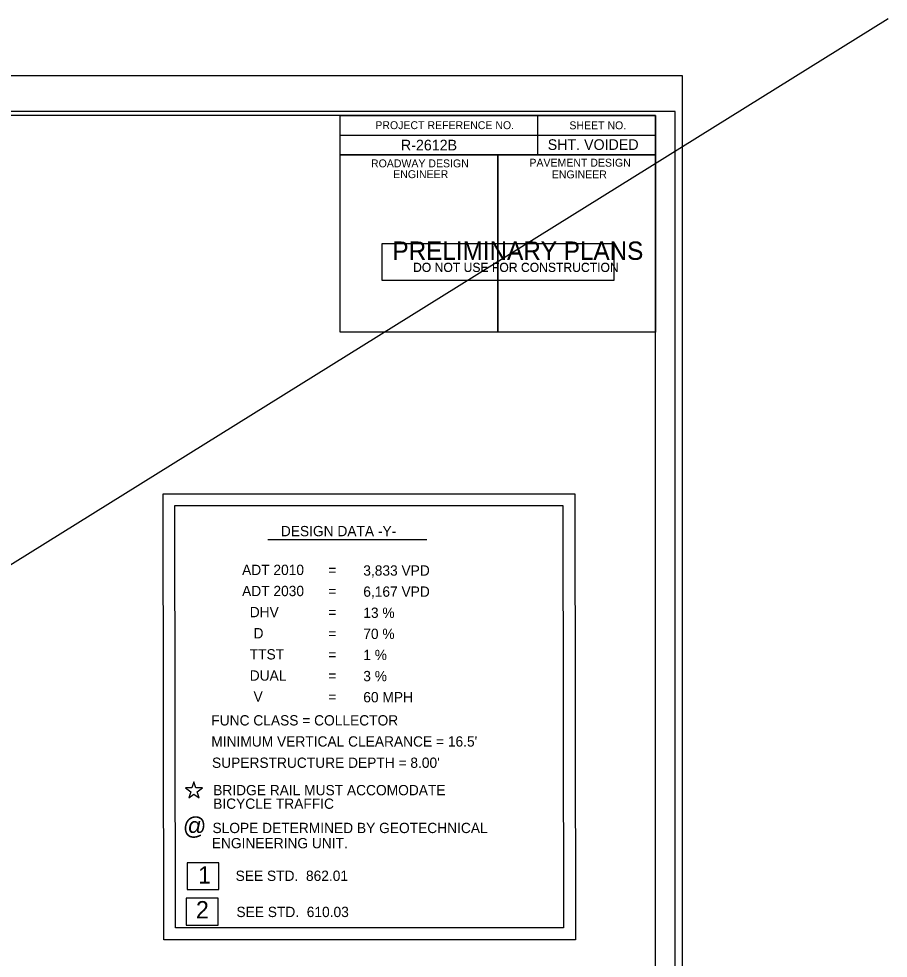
# Model space of a CAD drawing. Extents: x 573813 to 575363, y -54752 to -53123.
# Drawn here: x 574087.2 to 574197.6, y -54636.2 to -54516.9 of the extents above; entities that cross this region are included whole.
import ezdxf

# ---------------------------------------------------------------- set-up
doc = ezdxf.new("R2010")
doc.units = 0
for name, color, linetype in [('Old_Level_11', 7, 'Continuous'), ('Prop RDY Traffic Signal CELL', 7, 'Continuous'), ('Sheet Data Field CELL', 7, 'Continuous'), ('Sheet Plot Border Inside CELL', 7, 'Continuous'), ('Sheet Plot Border Outside CELL', 7, 'Continuous'), ('Sheet Sticker Preliminary CELL', 7, 'Continuous'), ('Sheet Typical CELL', 7, 'Continuous')]:
    doc.layers.add(name, color=color, linetype=linetype)

msp = doc.modelspace()

# ---------------------------------------------------------------- linework, layer by layer
at = {"layer": 'Old_Level_11'}
for p, q in [((574197.59, -54516.9), (573819.63, -54751.97)), ((574118.8, -54583.01), (574138.99, -54583.01))]:
    msp.add_line(p, q, dxfattribs=at)
for points in [[(574105.51, -54577.2), (574157.78, -54577.2), (574157.88, -54633.8), (574105.61, -54633.8)], [(574107.01, -54578.7), (574156.28, -54578.7), (574156.37, -54632.3), (574107.1, -54632.3)], [(574108.55, -54627.44), (574112.59, -54627.44), (574112.59, -54624.04), (574108.55, -54624.04)], [(574108.45, -54631.95), (574112.5, -54631.95), (574112.5, -54628.55), (574108.45, -54628.55)]]:
    msp.add_lwpolyline(points, close=True, dxfattribs=at)
at = {"layer": 'Prop RDY Traffic Signal CELL'}
msp.add_lwpolyline([(574109.17, -54614.54), (574108.36, -54614.54), (574109.02, -54615.02), (574108.76, -54615.8), (574109.43, -54615.32), (574110.09, -54615.8), (574109.83, -54615.02), (574110.5, -54614.54), (574109.68, -54614.54), (574109.42, -54613.77), (574109.17, -54614.54)], dxfattribs=at)
at = {"layer": 'Sheet Plot Border Inside CELL'}
msp.add_lwpolyline([(574170.55, -54528.66), (573837.07, -54528.66), (573837.07, -54739.79), (574170.55, -54739.79)], close=True, dxfattribs=at)
at = {"layer": 'Sheet Plot Border Outside CELL'}
for p, q in [((574171.45, -54524.16), (573834.47, -54524.16)), ((574171.45, -54744.28), (574171.45, -54524.16))]:
    msp.add_line(p, q, dxfattribs=at)
msp.add_lwpolyline([(574171.45, -54524.16), (573834.47, -54524.16), (573834.47, -54744.28), (574171.45, -54744.28)], close=True, dxfattribs=at)
at = {"layer": 'Sheet Sticker Preliminary CELL'}
for points in [[(574133.33, -54550.11), (574133.33, -54545.41), (574162.74, -54545.41), (574162.74, -54550.11)], [(574133.33, -54550.14), (574133.33, -54545.44), (574162.74, -54545.44), (574162.74, -54550.14)]]:
    msp.add_lwpolyline(points, close=True, dxfattribs=at)
at = {"layer": 'Sheet Typical CELL'}
for p, q in [((574153.04, -54529.18), (574153.04, -54534.18)), ((574128.01, -54531.68), (574168.04, -54531.68)), ((574148.03, -54534.18), (574148.03, -54556.68))]:
    msp.add_line(p, q, dxfattribs=at)
for points in [[(574168.04, -54529.17), (573867.88, -54529.17), (573867.88, -54739.28), (574168.04, -54739.28)], [(574128.01, -54529.17), (574168.04, -54529.17), (574168.04, -54534.18), (574128.01, -54534.18)], [(574128.01, -54534.18), (574148.03, -54534.18), (574148.03, -54556.69), (574128.01, -54556.69)], [(574148.03, -54534.18), (574168.04, -54534.18), (574168.04, -54556.69), (574148.03, -54556.69)]]:
    msp.add_lwpolyline(points, close=True, dxfattribs=at)

# ---------------------------------------------------------------- texts
at = {"layer": 'Old_Level_11'}
for s, height, p in [('DESIGN DATA -Y-', 1.3063, (574120.46, -54582.59)), ('ADT 2010', 1.306, (574115.54, -54587.51)), ('3,833 VPD ', 1.306, (574130.93, -54587.59)), ('=', 1.31, (574126.48, -54587.53)), ('ADT 2030', 1.306, (574115.54, -54590.19)), ('=', 1.31, (574126.48, -54590.21)), ('6,167 VPD ', 1.306, (574130.93, -54590.27)), ('  DHV', 1.306, (574115.54, -54592.87)), ('=', 1.31, (574126.48, -54592.89)), ('13 %', 1.306, (574130.93, -54592.95)), ('   D', 1.306, (574115.54, -54595.55)), ('=', 1.31, (574126.48, -54595.58)), ('70 %', 1.306, (574130.93, -54595.63)), ('  TTST', 1.306, (574115.54, -54598.23)), ('1 %', 1.306, (574130.93, -54598.31)), ('=', 1.31, (574126.48, -54598.26)), ('  DUAL', 1.306, (574115.54, -54600.92)), ('=', 1.31, (574126.48, -54600.94)), ('3 %', 1.306, (574130.93, -54600.99)), ('   V', 1.306, (574115.54, -54603.6)), ('=', 1.31, (574126.48, -54603.62)), ('60 MPH', 1.306, (574130.93, -54603.67)), ('FUNC CLASS = COLLECTOR', 1.3063, (574111.63, -54606.61)), ("MINIMUM VERTICAL CLEARANCE = 16.5'", 1.3063, (574111.63, -54609.29)), ("SUPERSTRUCTURE DEPTH = 8.00'", 1.3063, (574111.72, -54611.99)), ('BRIDGE RAIL MUST ACCOMODATE ', 1.3063, (574111.87, -54615.47)), ('BICYCLE TRAFFIC', 1.3063, (574111.87, -54617.19)), ('@', 2.2, (574108.02, -54620.44)), ('SLOPE DETERMINED BY GEOTECHNICAL', 1.3063, (574111.78, -54620.27)), ('ENGINEERING UNIT.', 1.3063, (574111.69, -54622.2)), ('1', 2.2, (574109.95, -54626.69)), ('SEE STD.  862.01', 1.3063, (574114.72, -54626.34)), ('2', 2.2, (574109.68, -54631.1)), ('SEE STD.  610.03', 1.3063, (574114.82, -54630.93))]:
    msp.add_text(s, height=height, rotation=0.0001, dxfattribs=at).set_placement(p)
at = {"layer": 'Sheet Data Field CELL'}
for s, height, p in [('R-2612B  ', 1.351, (574135.71, -54533.61)), ('SHT. VOIDED', 1.3507, (574154.35, -54533.55))]:
    msp.add_text(s, height=height, dxfattribs=at).set_placement(p)
at = {"layer": 'Sheet Sticker Preliminary CELL'}
for s, height, p in [('PRELIMINARY PLANS', 2.3052, (574134.63, -54547.48)), ('PRELIMINARY PLANS', 2.3052, (574134.63, -54547.51)), ('DO NOT USE FOR CONSTRUCTION', 1.1526, (574137.25, -54549.02)), ('DO NOT USE FOR CONSTRUCTION', 1.1526, (574137.25, -54549.02)), ('DO NOT USE FOR CONSTRUCTION', 1.1526, (574137.25, -54549.05)), ('DO NOT USE FOR CONSTRUCTION', 1.1526, (574137.25, -54549.05))]:
    msp.add_text(s, height=height, dxfattribs=at).set_placement(p)
at = {"layer": 'Sheet Typical CELL'}
for s, height, p in [('PROJECT REFERENCE NO.', 1.0006, (574132.46, -54530.91)), ('SHEET NO.', 1.001, (574157.1, -54530.93)), ('ROADWAY DESIGN', 1.0006, (574131.91, -54535.76)), ('PAVEMENT DESIGN', 1.0006, (574152.03, -54535.67)), ('ENGINEER', 1.001, (574134.73, -54537.13)), ('ENGINEER', 1.001, (574154.87, -54537.16))]:
    msp.add_text(s, height=height, dxfattribs=at).set_placement(p)

doc.saveas('drawing.dxf')
